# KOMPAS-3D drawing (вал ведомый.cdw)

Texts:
  Вал ведомый
  ЛОБАН АЛЕКСАНДР МИХАЙЛОВИЧ
  Ось цетров
  отв.центр. Е6
  ГОСТ 14034-74
  отв.цетр.F М6
  ГОСТ14034-74
  170...190 НВ
  Неуказанные предельные откланения размеров: охватываемых -
  h14, охватывающих - H14, прочих -±0,5IT14
  Ra  10
  gost5_RGB_0_0_0_SC_0.5_THICK_0.2
  ByLayer_RGB_255_0_0_THICK_0.2
  Сталь 40Х ГОСТ 4543-71
Dimensions and other numbers on the sheet: 40; 0,004; 72; 37; 50; 2; 2 фаски; 13; 12; 14; 16; 44; 49.5; 0,3; 3; 0.5; 1; 55; 54; 0,5; 5; 1.6; 3 фаски; 65; 0,02; 0,01; 56; 10; 202; 45; 268; 22; 6; 0.022; 0,086; 4; 1:1; 0; 7; 8; 9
